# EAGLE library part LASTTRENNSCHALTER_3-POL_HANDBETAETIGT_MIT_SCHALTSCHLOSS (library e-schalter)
Lasttrennschalter handbetätigt mit Schaltschloss, 3-pol.
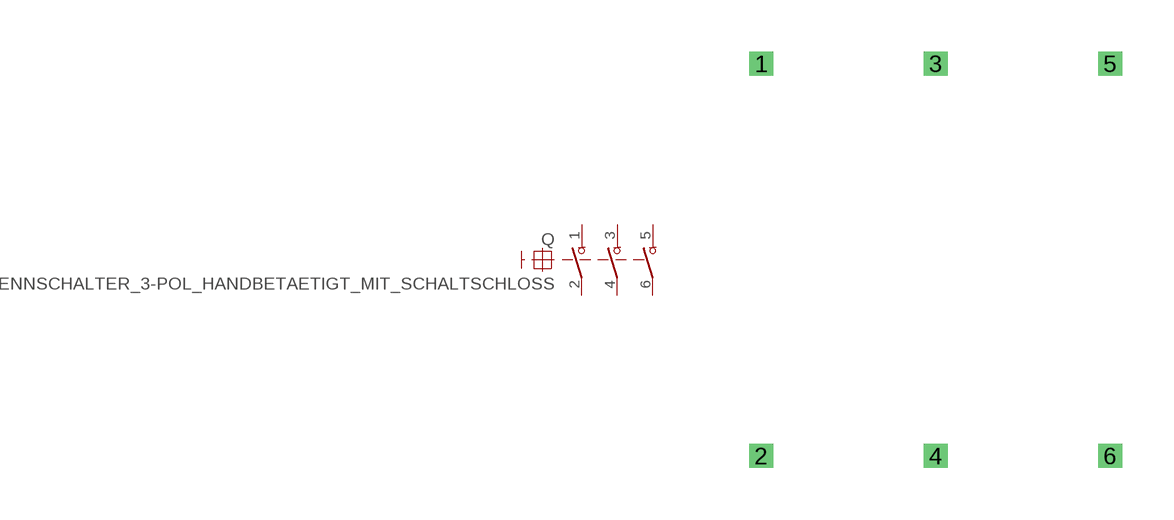
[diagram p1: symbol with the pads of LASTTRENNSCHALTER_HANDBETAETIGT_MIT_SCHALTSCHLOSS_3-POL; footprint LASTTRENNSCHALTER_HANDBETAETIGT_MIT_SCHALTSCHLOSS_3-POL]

Designator prefix Q

## LASTTRENNSCHALTER_3-POL_HANDBETAETIGT_MIT_SCHALTSCHLOSS  [LASTTRENNSCHALTER_HANDBETAETIGT_MIT_SCHALTSCHLOSS_3-POL]
1  1  pas
2  2  pas
3  3  pas
4  4  pas
5  5  pas
6  6  pas

## Footprint LASTTRENNSCHALTER_HANDBETAETIGT_MIT_SCHALTSCHLOSS_3-POL (pad centres in mm)
Dummy
drill 0.2 pad 0.6 square: 1 -5.08,5.715; 2 -5.08,-5.715; 3 0,5.715; 4 0,-5.715; 5 5.08,5.715; 6 5.08,-5.715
